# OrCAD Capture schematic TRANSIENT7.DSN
size A
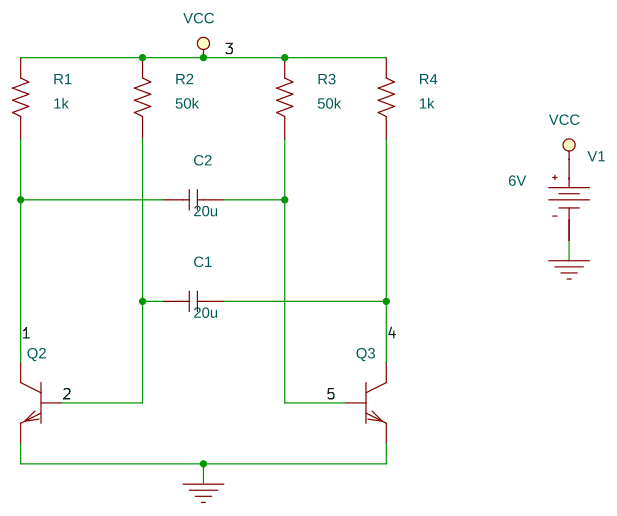
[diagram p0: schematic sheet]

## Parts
C1  20u  [RAD/CK05]
C2  20u  [RAD/CK05]
Q2  QbreakN
Q3  QbreakN
R1  1k  [AX/RC05]
R2  50k  [AX/RC05]
R3  50k  [AX/RC05]
R4  1k  [AX/RC05]
V1  VDC

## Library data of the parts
C1 C2 = C: IC: 0
Q2 Q3 = QbreakN
R1-R4 = R
V1 = VDC: DC: 6V

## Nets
VCC: R1.2 R2.2 R3.2 R4.2 V1.0(+)
0: Q2.2(e) Q3.2(e) V1.1(-)
1: C2.1 Q2.1(c) R1.1
2: C1.1 Q2.0(b) R2.1
4: C1.2 Q3.1(c) R4.1
5: C2.2 Q3.0(b) R3.1
